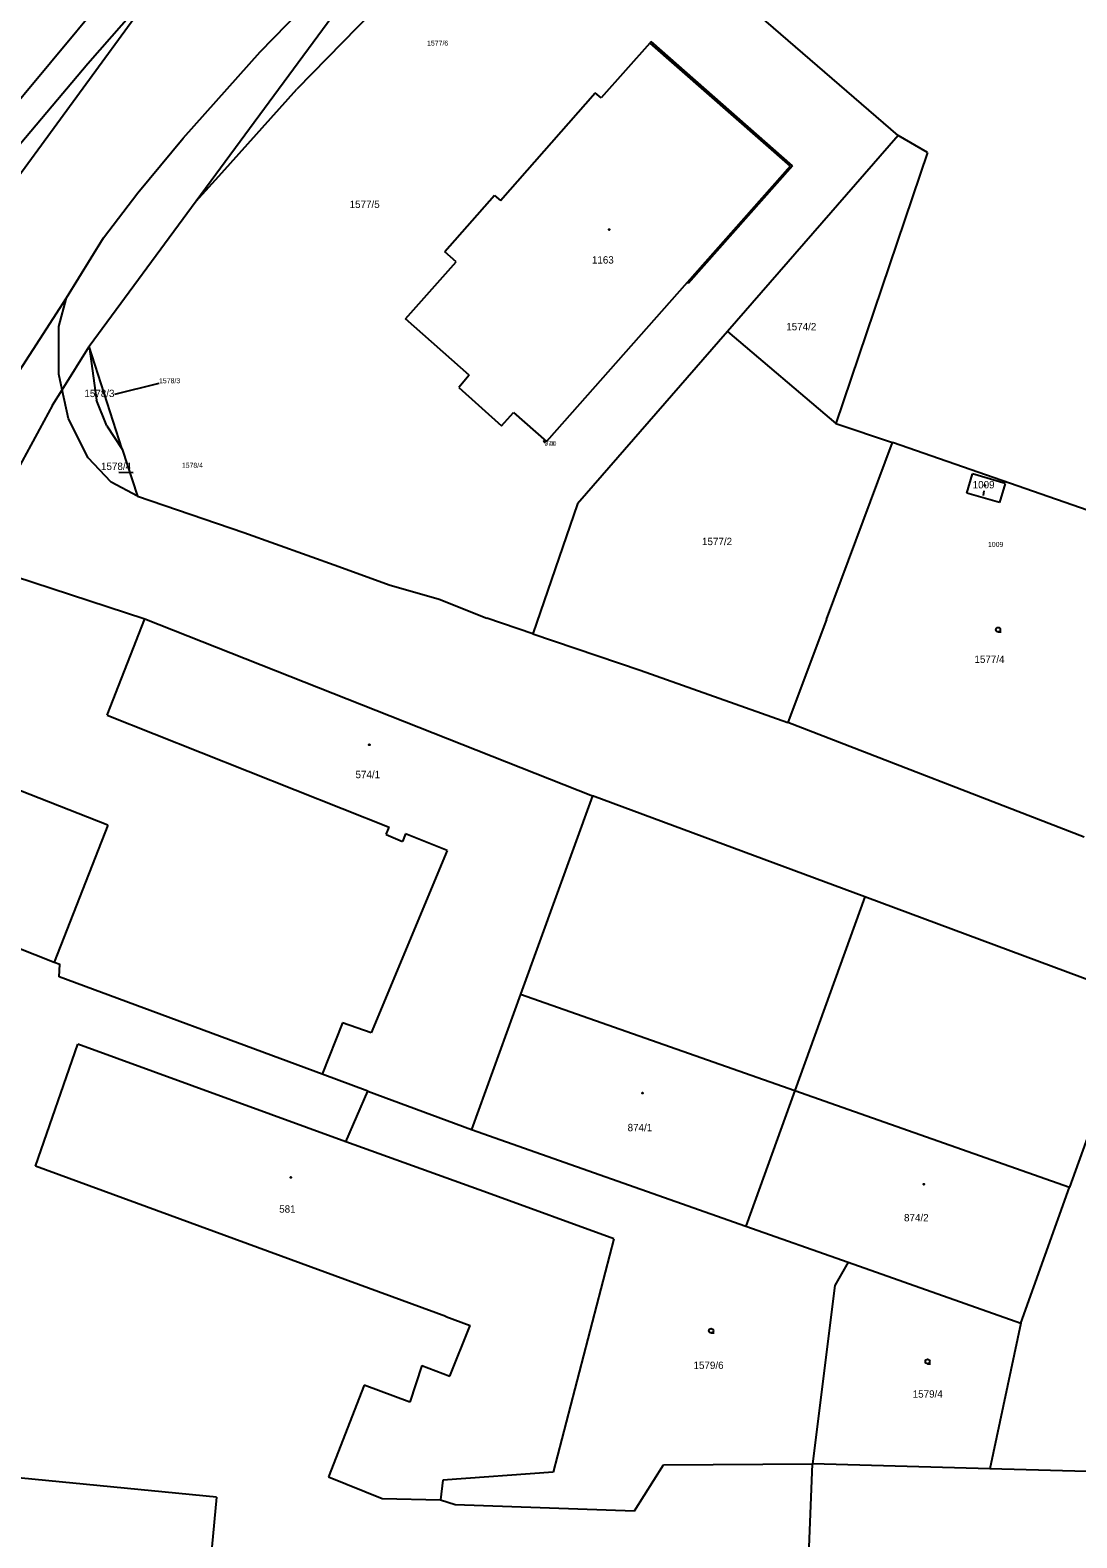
# Model space of a CAD drawing. Extents: x -866624 to -866276, y -1050208 to -1049940.
# Drawn here: x -866412 to -866340.8, y -1050100.7 to -1049998.1 of the extents above; entities that cross this region are included whole.
import ezdxf

# ---------------------------------------------------------------- set-up
doc = ezdxf.new("R2010")
doc.units = 0
for name, color, linetype in [('bod-cislo', 7, 'Continuous'), ('bod-oznac', 7, 'Continuous'), ('bod-vyska', 7, 'Continuous'), ('Default', 7, 'Continuous'), ('Hranice', 7, 'Continuous'), ('Hranice další', 7, 'Continuous'), ('Hranice-budov', 7, 'Continuous'), ('Parcela-pozemkova', 7, 'Continuous'), ('Parcela-stavebni', 7, 'Continuous'), ('Parcelni-cisla-pomocna', 7, 'Continuous'), ('znacky-budov', 7, 'Continuous'), ('Znacky-kultury', 7, 'Continuous')]:
    doc.layers.add(name, color=color, linetype=linetype)

# ---------------------------------------------------------------- blocks, each defined once
blk = doc.blocks.new('p_zahr')
at = {"layer": 'Default'}
blk.add_line((0, -0.75), (0.99, -0.75), dxfattribs=at)
blk.add_circle((0, 0), 0.75, dxfattribs=at)
blk = doc.blocks.new('s_zdena')
at = {"layer": 'Default'}
blk.add_circle((0, 0), 0.175, dxfattribs=at)
for start, end in [(0, 180), (180, 0)]:
    blk.add_arc((0, 0), 0.0875, start, end, dxfattribs=at)
blk = doc.blocks.new('POINT_DISPLAY')
at = {"layer": 'Default'}
for p, q in [((-0.07, 0.07), (0.07, -0.07)), ((0.07, 0.07), (-0.07, -0.07))]:
    blk.add_line(p, q, dxfattribs=at)

msp = doc.modelspace()

# ---------------------------------------------------------------- linework, layer by layer
at = {"layer": 'Hranice'}
for p, q in [((-866352.98, -1050005.3), (-866376.44, -1049985.01)), ((-866396.38, -1049999.59), (-866389.15, -1049992.21)), ((-866425.65, -1050025.61), (-866402.57, -1049994.04)), ((-866386.74, -1049994.84), (-866393.89, -1050002.14)), ((-866406.93, -1049995.89), (-866414.35, -1050004.79)), ((-866404.17, -1049995.92), (-866408.09, -1050000.42)), ((-866390.8, -1049996.3), (-866400.72, -1050009.76)), ((-866369.88, -1049999), (-866369.79, -1049998.9)), ((-866360.17, -1050007.35), (-866369.79, -1049998.9)), ((-866401.62, -1050005.48), (-866396.38, -1049999.59)), ((-866369.88, -1049999), (-866373.19, -1050002.74)), ((-866408.09, -1050000.42), (-866414.04, -1050007.46)), ((-866398.99, -1050007.83), (-866393.89, -1050002.14)), ((-866380.03, -1050009.7), (-866373.58, -1050002.4)), ((-866373.19, -1050002.74), (-866373.58, -1050002.4)), ((-866404.69, -1050009.18), (-866401.62, -1050005.48)), ((-866352.98, -1050005.3), (-866364.58, -1050018.61)), ((-866350.98, -1050006.44), (-866352.98, -1050005.3)), ((-866350.98, -1050006.44), (-866357.21, -1050024.88)), ((-866400.72, -1050009.76), (-866398.99, -1050007.83)), ((-866360.17, -1050007.35), (-866367.26, -1050015.36)), ((-866407.02, -1050012.24), (-866404.69, -1050009.18)), ((-866400.72, -1050009.76), (-866408, -1050019.64)), ((-866380.44, -1050009.37), (-866383.81, -1050013.2)), ((-866380.44, -1050009.37), (-866380.03, -1050009.7)), ((-866409.54, -1050016.33), (-866407.02, -1050012.24)), ((-866383.04, -1050013.89), (-866383.81, -1050013.2)), ((-866386.5, -1050017.76), (-866383.04, -1050013.89)), ((-866367.34, -1050015.29), (-866376.9, -1050026.1)), ((-866367.26, -1050015.36), (-866367.34, -1050015.29)), ((-866423.27, -1050037.5), (-866409.54, -1050016.33)), ((-866410.06, -1050018.28), (-866409.54, -1050016.33)), ((-866410.06, -1050021.53), (-866410.06, -1050018.28)), ((-866382.16, -1050021.58), (-866386.5, -1050017.76)), ((-866364.58, -1050018.61), (-866374.79, -1050030.34)), ((-866364.58, -1050018.61), (-866357.21, -1050024.88)), ((-866409.84, -1050022.58), (-866408, -1050019.64)), ((-866408, -1050019.64), (-866407.51, -1050023.3)), ((-866405.75, -1050026.62), (-866408, -1050019.64)), ((-866409.84, -1050022.58), (-866410.06, -1050021.53)), ((-866382.16, -1050021.58), (-866382.87, -1050022.44)), ((-866382.87, -1050022.44), (-866379.95, -1050025.04)), ((-866410.49, -1050023.63), (-866409.84, -1050022.58)), ((-866409.42, -1050024.55), (-866409.84, -1050022.58)), ((-866406.81, -1050025.03), (-866407.51, -1050023.3)), ((-866410.49, -1050023.63), (-866416.26, -1050034.23)), ((-866408.07, -1050027.21), (-866409.42, -1050024.55)), ((-866379.95, -1050025.04), (-866379.15, -1050024.12)), ((-866379.15, -1050024.12), (-866376.9, -1050026.1)), ((-866406.81, -1050025.03), (-866405.75, -1050026.62)), ((-866357.21, -1050024.88), (-866353.36, -1050026.16)), ((-866405.75, -1050026.62), (-866404.72, -1050029.81)), ((-866357.86, -1050038.2), (-866353.36, -1050026.16)), ((-866332.37, -1050033.48), (-866353.36, -1050026.16)), ((-866406.5, -1050028.86), (-866408.07, -1050027.21)), ((-866348.31, -1050029.62), (-866347.93, -1050028.31)), ((-866345.7, -1050028.95), (-866347.93, -1050028.31)), ((-866404.72, -1050029.81), (-866406.5, -1050028.86)), ((-866346.08, -1050030.26), (-866348.31, -1050029.62)), ((-866345.7, -1050028.95), (-866346.08, -1050030.26)), ((-866404.72, -1050029.81), (-866397.49, -1050032.29)), ((-866374.79, -1050030.34), (-866377.83, -1050039.18)), ((-866397.49, -1050032.29), (-866391.03, -1050034.6)), ((-866416.26, -1050034.23), (-866404.22, -1050038.17)), ((-866391.03, -1050034.6), (-866387.6, -1050035.85)), ((-866387.6, -1050035.85), (-866384.2, -1050036.82)), ((-866384.2, -1050036.82), (-866380.96, -1050038.11)), ((-866404.22, -1050038.17), (-866373.78, -1050050.19)), ((-866377.83, -1050039.18), (-866380.96, -1050038.11)), ((-866357.86, -1050038.2), (-866360.48, -1050045.22)), ((-866377.83, -1050039.18), (-866370.53, -1050041.66)), ((-866370.53, -1050041.66), (-866360.48, -1050045.22)), ((-866340.32, -1050053.01), (-866360.48, -1050045.22)), ((-866373.78, -1050050.19), (-866378.66, -1050063.69)), ((-866355.25, -1050057.08), (-866373.78, -1050050.19)), ((-866355.25, -1050057.08), (-866360, -1050070.25)), ((-866336.71, -1050063.98), (-866355.25, -1050057.08)), ((-866417.99, -1050058.51), (-866410.39, -1050061.51)), ((-866410.39, -1050061.51), (-866410, -1050061.66)), ((-866410.05, -1050062.51), (-866410, -1050061.66)), ((-866392.16, -1050069.13), (-866410.05, -1050062.51)), ((-866378.66, -1050063.69), (-866381.99, -1050072.9)), ((-866336.71, -1050063.98), (-866341.33, -1050076.81)), ((-866389.06, -1050070.28), (-866392.16, -1050069.13)), ((-866390.54, -1050073.73), (-866389.06, -1050070.28)), ((-866389.06, -1050070.28), (-866381.99, -1050072.9)), ((-866360, -1050070.25), (-866363.33, -1050079.47)), ((-866380.92, -1050077.21), (-866390.54, -1050073.73)), ((-866381.99, -1050072.9), (-866363.33, -1050079.47)), ((-866344.63, -1050086.06), (-866341.33, -1050076.81)), ((-866372.31, -1050080.32), (-866380.92, -1050077.21)), ((-866363.33, -1050079.47), (-866356.38, -1050081.92)), ((-866372.31, -1050080.32), (-866376.45, -1050096.19)), ((-866356.38, -1050081.92), (-866357.29, -1050083.51)), ((-866356.38, -1050081.92), (-866344.63, -1050086.06)), ((-866357.29, -1050083.51), (-866358.8, -1050095.64)), ((-866344.63, -1050086.06), (-866346.74, -1050095.97)), ((-866376.45, -1050096.19), (-866383.94, -1050096.75)), ((-866370.91, -1050098.83), (-866368.95, -1050095.7)), ((-866368.95, -1050095.7), (-866358.8, -1050095.64)), ((-866359.18, -1050105.1), (-866358.8, -1050095.64)), ((-866346.74, -1050095.97), (-866358.8, -1050095.64)), ((-866317.7, -1050096.76), (-866346.74, -1050095.97)), ((-866383.94, -1050096.75), (-866384.1, -1050098.08)), ((-866384.1, -1050098.08), (-866383.1, -1050098.39)), ((-866383.1, -1050098.39), (-866370.91, -1050098.83))]:
    msp.add_line(p, q, dxfattribs=at)
at = {"layer": 'Hranice další'}
for p, q in [((-866369.88, -1049999), (-866360.33, -1050007.38)), ((-866360.33, -1050007.38), (-866367.34, -1050015.29)), ((-866406.77, -1050044.71), (-866404.22, -1050038.17)), ((-866406.77, -1050044.71), (-866387.61, -1050052.33)), ((-866406.73, -1050052.2), (-866414.06, -1050049.31)), ((-866406.73, -1050052.2), (-866410.39, -1050061.51)), ((-866387.81, -1050052.84), (-866387.61, -1050052.33)), ((-866387.81, -1050052.84), (-866386.7, -1050053.31)), ((-866386.49, -1050052.78), (-866386.7, -1050053.31)), ((-866383.65, -1050053.91), (-866386.49, -1050052.78)), ((-866383.65, -1050053.91), (-866388.82, -1050066.32)), ((-866378.66, -1050063.69), (-866360, -1050070.25)), ((-866390.78, -1050065.63), (-866392.16, -1050069.13)), ((-866388.82, -1050066.32), (-866390.78, -1050065.63)), ((-866411.65, -1050075.39), (-866408.77, -1050067.08)), ((-866390.54, -1050073.73), (-866408.77, -1050067.08)), ((-866360, -1050070.25), (-866341.33, -1050076.81)), ((-866383.75, -1050085.61), (-866411.65, -1050075.39)), ((-866383.75, -1050085.61), (-866382.08, -1050086.22)), ((-866383.48, -1050089.68), (-866382.08, -1050086.22)), ((-866385.37, -1050088.94), (-866386.2, -1050091.44)), ((-866385.37, -1050088.94), (-866383.48, -1050089.68)), ((-866389.3, -1050090.29), (-866391.73, -1050096.51)), ((-866386.2, -1050091.44), (-866389.3, -1050090.29)), ((-866399.34, -1050097.9), (-866413.54, -1050096.51)), ((-866391.73, -1050096.51), (-866388.07, -1050098)), ((-866399.34, -1050097.9), (-866399.92, -1050103.96)), ((-866388.07, -1050098), (-866384.1, -1050098.08))]:
    msp.add_line(p, q, dxfattribs=at)
at = {"layer": 'Hranice-budov'}
for p, q in [((-866369.88, -1049999), (-866373.19, -1050002.74)), ((-866369.88, -1049999), (-866360.33, -1050007.38)), ((-866380.03, -1050009.7), (-866373.58, -1050002.4)), ((-866373.19, -1050002.74), (-866373.58, -1050002.4)), ((-866360.33, -1050007.38), (-866367.34, -1050015.29)), ((-866380.44, -1050009.37), (-866383.81, -1050013.2)), ((-866380.44, -1050009.37), (-866380.03, -1050009.7)), ((-866383.04, -1050013.89), (-866383.81, -1050013.2)), ((-866386.5, -1050017.76), (-866383.04, -1050013.89)), ((-866367.34, -1050015.29), (-866376.9, -1050026.1)), ((-866382.16, -1050021.58), (-866386.5, -1050017.76)), ((-866382.16, -1050021.58), (-866382.87, -1050022.44)), ((-866382.87, -1050022.44), (-866379.95, -1050025.04)), ((-866379.95, -1050025.04), (-866379.15, -1050024.12)), ((-866379.15, -1050024.12), (-866376.9, -1050026.1)), ((-866348.31, -1050029.62), (-866347.93, -1050028.31)), ((-866345.7, -1050028.95), (-866347.93, -1050028.31)), ((-866346.08, -1050030.26), (-866348.31, -1050029.62)), ((-866345.7, -1050028.95), (-866346.08, -1050030.26)), ((-866406.77, -1050044.71), (-866404.22, -1050038.17)), ((-866404.22, -1050038.17), (-866373.78, -1050050.19)), ((-866406.77, -1050044.71), (-866387.61, -1050052.33)), ((-866373.78, -1050050.19), (-866378.66, -1050063.69)), ((-866387.81, -1050052.84), (-866387.61, -1050052.33)), ((-866387.81, -1050052.84), (-866386.7, -1050053.31)), ((-866386.49, -1050052.78), (-866386.7, -1050053.31)), ((-866383.65, -1050053.91), (-866386.49, -1050052.78)), ((-866383.65, -1050053.91), (-866388.82, -1050066.32)), ((-866378.66, -1050063.69), (-866381.99, -1050072.9)), ((-866378.66, -1050063.69), (-866381.99, -1050072.9)), ((-866378.66, -1050063.69), (-866360, -1050070.25)), ((-866390.78, -1050065.63), (-866392.16, -1050069.13)), ((-866388.82, -1050066.32), (-866390.78, -1050065.63)), ((-866411.65, -1050075.39), (-866408.77, -1050067.08)), ((-866390.54, -1050073.73), (-866408.77, -1050067.08)), ((-866389.06, -1050070.28), (-866392.16, -1050069.13)), ((-866389.06, -1050070.28), (-866381.99, -1050072.9)), ((-866360, -1050070.25), (-866363.33, -1050079.47)), ((-866360, -1050070.25), (-866363.33, -1050079.47)), ((-866360, -1050070.25), (-866341.33, -1050076.81)), ((-866380.92, -1050077.21), (-866390.54, -1050073.73)), ((-866381.99, -1050072.9), (-866363.33, -1050079.47)), ((-866383.75, -1050085.61), (-866411.65, -1050075.39)), ((-866344.63, -1050086.06), (-866341.33, -1050076.81)), ((-866372.31, -1050080.32), (-866380.92, -1050077.21)), ((-866363.33, -1050079.47), (-866356.38, -1050081.92)), ((-866372.31, -1050080.32), (-866376.45, -1050096.19)), ((-866356.38, -1050081.92), (-866344.63, -1050086.06)), ((-866383.75, -1050085.61), (-866382.08, -1050086.22)), ((-866383.48, -1050089.68), (-866382.08, -1050086.22)), ((-866385.37, -1050088.94), (-866386.2, -1050091.44)), ((-866385.37, -1050088.94), (-866383.48, -1050089.68)), ((-866389.3, -1050090.29), (-866391.73, -1050096.51)), ((-866386.2, -1050091.44), (-866389.3, -1050090.29)), ((-866376.45, -1050096.19), (-866383.94, -1050096.75)), ((-866391.73, -1050096.51), (-866388.07, -1050098)), ((-866383.94, -1050096.75), (-866384.1, -1050098.08)), ((-866388.07, -1050098), (-866384.1, -1050098.08))]:
    msp.add_line(p, q, dxfattribs=at)
at = {"layer": 'Parcelni-cisla-pomocna'}
for p, q in [((-866406.27, -1050022.88), (-866403.25, -1050022.14)), ((-866405.02, -1050028.23), (-866405.99, -1050028.21)), ((-866347.18, -1050029.78), (-866347.14, -1050029.46))]:
    msp.add_line(p, q, dxfattribs=at)

# ---------------------------------------------------------------- block references
at = {"layer": 'bod-oznac'}
msp.add_blockref('POINT_DISPLAY', (-866377.03, -1050026.09), dxfattribs=at)
at = {"layer": 'znacky-budov', "xscale": 0.2, "yscale": 0.20000000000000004}
for p in [(-866372.64, -1050011.69), (-866347.09, -1050029.09), (-866388.95, -1050046.73), (-866370.37, -1050070.42), (-866394.29, -1050076.15), (-866351.24, -1050076.62)]:
    msp.add_blockref('s_zdena', p, dxfattribs=at)
at = {"layer": 'Znacky-kultury', "xscale": 0.2, "yscale": 0.20000000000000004}
for p in [(-866346.18, -1050038.9), (-866365.7, -1050086.58), (-866350.98, -1050088.67)]:
    msp.add_blockref('p_zahr', p, dxfattribs=at)

# ---------------------------------------------------------------- texts
at = {"layer": 'bod-cislo'}
msp.add_text('778', height=0.3, dxfattribs=at).set_placement((-866377.03, -1050026.39))
at = {"layer": 'bod-vyska'}
msp.add_text('0 00', height=0.3, dxfattribs=at).set_placement((-866377.03, -1050026.39))
at = {"layer": 'Parcela-pozemkova'}
for s, p in [('1577/5', (-866390.29, -1050010.22)), ('1574/2', (-866360.59, -1050018.54)), ('1578/3', (-866408.33, -1050023.08)), ('1578/4', (-866407.2, -1050028.04)), ('1577/2', (-866366.32, -1050033.15)), ('1577/4', (-866347.79, -1050041.16)), ('1579/6', (-866366.9, -1050089.18)), ('1579/4', (-866351.99, -1050091.13))]:
    msp.add_text(s, height=0.5, dxfattribs=at).set_placement(p)
at = {"layer": 'Parcela-stavebni'}
for s, p in [('1163', (-866373.81, -1050014)), ('1009', (-866347.91, -1050029.29)), ('574/1', (-866389.89, -1050049)), ('874/1', (-866371.38, -1050073.01)), ('581', (-866395.08, -1050078.55)), ('874/2', (-866352.58, -1050079.14))]:
    msp.add_text(s, height=0.5, dxfattribs=at).set_placement(p)
at = {"layer": 'Parcelni-cisla-pomocna'}
for s, p in [('1577/6', (-866385.02, -1049999.18)), ('1578/3', (-866403.25, -1050022.14)), ('1578/4', (-866401.7, -1050027.89)), ('1009', (-866346.87, -1050033.27))]:
    msp.add_text(s, height=0.34, dxfattribs=at).set_placement(p)

doc.saveas('drawing.dxf')
